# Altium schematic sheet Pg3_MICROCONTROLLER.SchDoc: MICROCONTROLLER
size 431 x 279 mm; Date: Not shown in title block; ApprovedBy: Not shown in title block; CheckedBy: Not shown in title block; Author: Not shown in title block; CompanyName: Not shown in title block; Engineer: Not shown in title block; Organization: Not shown in title block; Address1: Not shown in title block; Address2: Not shown in title block; Address3: Not shown in title block; Address4: Not shown in title block; DocumentNumber: 3; Revision: Use project parameter SCH_Rev; SheetNumber: 3; SheetTotal: 9; PageSetup: Record=PageOptions|CenterHorizontal=True|CenterVertical=True|PrintScale=1.00|XCorrection=1.00|YCorrection=1.00|PrintKind=0|BorderSize=5000000|LeftOffset=0|BottomOffset=0|Orientation=2|PaperLength=1000|PaperWidth=1000|Scale=100|PaperSource=15|PrintQuality=600|MediaType=1|DitherType=10|PaperKind=Letter|PrintScaleMode=1
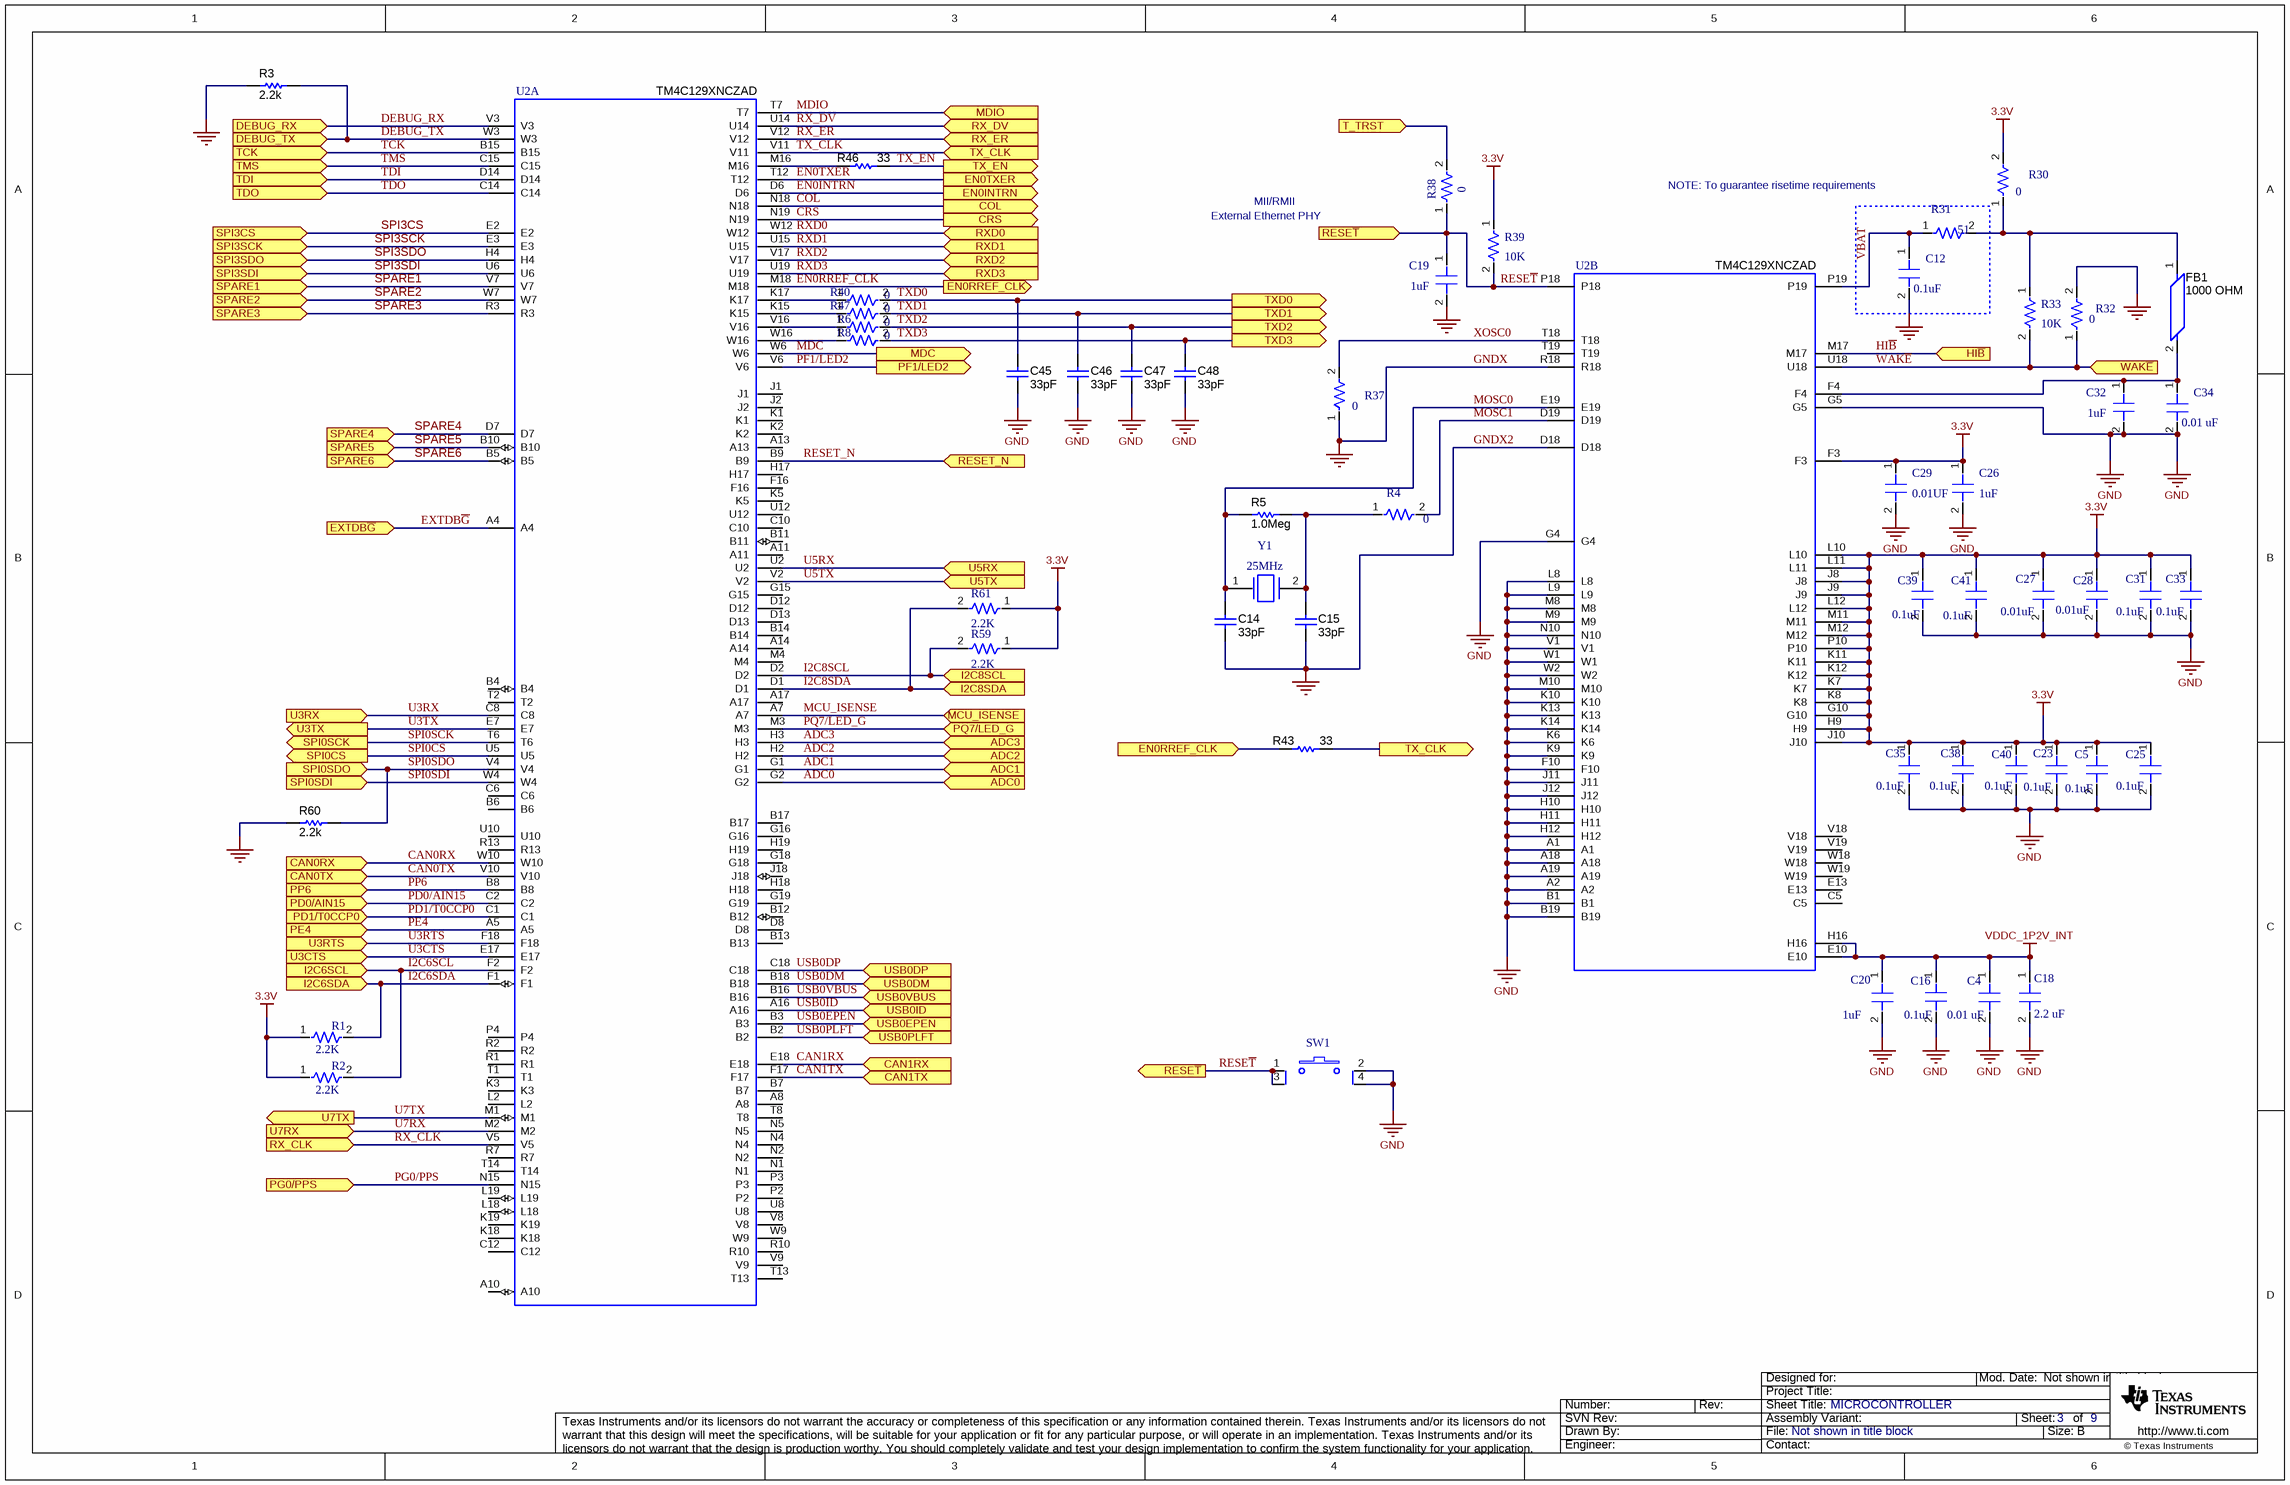
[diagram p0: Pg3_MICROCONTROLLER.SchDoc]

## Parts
C4  value 0.01 uF  [0402]  (hidden comment: CAPC0603)
C5  value 0.1uF  [0603]  (hidden comment: CAPC0603)
C12  value 0.1uF  [0603]  (hidden comment: CAPC0603)
C14  ValueDisplayed: 33pF  [0402]  (hidden comment: GRM1555C1H330JA01D)
C15  ValueDisplayed: 33pF  [0402]  (hidden comment: GRM1555C1H330JA01D)
C16  value 0.1uF  [0603]  (hidden comment: CAPC0603)
C18  value 2.2 uF  [0603]  (hidden comment: CAPC0603)
C19  value 1uF  [0402]  (hidden comment: CAPC0402)
C20  value 1uF  [0402]  (hidden comment: CAPC0402)
C23  value 0.1uF  [0603]  (hidden comment: CAPC0603)
C25  value 0.1uF  [0603]  (hidden comment: CAPC0603)
C26  value 1uF  [0402]  (hidden comment: CAPC0402)
C27  value 0.01uF  [0402]  (hidden comment: CAPC0603)
C28  value 0.01uF  [0402]  (hidden comment: CAPC0603)
C29  value 0.01UF  [0402]  (hidden comment: CAPC0402)
C31  value 0.1uF  [0402]  (hidden comment: CAPC0402)
C32  value 1uF  [0402]  (hidden comment: CAPC0402)
C33  value 0.1uF  [0402]  (hidden comment: CAPC0402)
C34  value 0.01 uF  [0402]  (hidden comment: CAPC0402)
C35  value 0.1uF  [0603]  (hidden comment: CAPC0603)
C38  value 0.1uF  [0603]  (hidden comment: CAPC0603)
C39  value 0.1uF  [0603]  (hidden comment: CAPC0603)
C40  value 0.1uF  [0603]  (hidden comment: CAPC0603)
C41  value 0.1uF  [0603]  (hidden comment: CAPC0603)
C45  ValueDisplayed: 33pF  [0402]  (hidden comment: GRM1555C1H330JA01D)
C46  ValueDisplayed: 33pF  [0402]  (hidden comment: GRM1555C1H330JA01D)
C47  ValueDisplayed: 33pF  [0402]  (hidden comment: GRM1555C1H330JA01D)
C48  ValueDisplayed: 33pF  [0402]  (hidden comment: GRM1555C1H330JA01D)
FB1  1000 OHM  [0603L]
R1  value 2.2K  [0603]  (hidden comment: RESC0603)
R2  value 2.2K  [0603]  (hidden comment: RESC0603)
R3  value 2.2k  [0402]  (hidden comment: CRCW04022K20JNED)
R4  value 0  [0402]  (hidden comment: RESC0402)
R5  value 1.0Meg  [0402]  (hidden comment: CRCW04021M00JNED)
R6  value 0  [0402]  (hidden comment: RESC0402)
R8  value 0  [0402]  (hidden comment: RESC0402)
R30  value 0  [0402]  (hidden comment: RESC0402)
R31  value 51  [0402]  (hidden comment: RESC0402)
R32  value 0  [0402]  (hidden comment: RESC0402)
R33  value 10K  [0402]  (hidden comment: RESC0402)
R37  value 0  [0402]  (hidden comment: RESC0402)
R38  value 0  [0402]  (hidden comment: RESC0402)
R39  value 10K  [0402]  (hidden comment: RESC0402)
R40  value 0  [0402]  (hidden comment: RESC0402)
R43  value 33  [0402]  (hidden comment: CRCW040233R0JNED)
R46  value 33  [0402]  (hidden comment: CRCW040233R0JNED)
R47  value 0  [0402]  (hidden comment: RESC0402)
R59  value 2.2K  [0603]  (hidden comment: RESC0603)
R60  value 2.2k  [0402]  (hidden comment: CRCW04022K20JNED)
R61  value 2.2K  [0603]  (hidden comment: RESC0603)
SW1  SW-EVQQ2  [SW-EVQQ2]  (value not drawn)
U2  Part Number: TM4C129XNCZAD  [BGA212C50P19X19_1000X1000X100]  (hidden comment: TM4C129X)  (parts A,B of 3)
Y1  value 25MHz  [XTAL-NX5032GA]  (hidden comment: XTAL-NX5032GA)

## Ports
ADC0, ADC1, ADC2, ADC3, CAN0RX, CAN0TX, CAN1RX, CAN1TX, COL, CRS, DEBUG_RX, DEBUG_TX, EN0INTRN, EN0RREF_CLK, EN0TXER, EXTDB~{G}, HI~{B}, I2C6SCL, I2C6SDA, I2C8SCL, I2C8SDA, MCU_ISENSE, MDC, MDIO, PD0/AIN15, PD1/T0CCP0, PE4, PF1/LED2, PG0/PPS, PP6, PQ7/LED_G, RESET_N, RESE~{T}, RX_CLK, RX_DV, RX_ER, RXD0, RXD1, RXD2, RXD3, SPARE1, SPARE2, SPARE3, SPARE4, SPARE5, SPARE6 (in), SPI0CS, SPI0SCK (out), SPI0SDI, SPI0SDO, SPI3CS, SPI3SCK, SPI3SDI, SPI3SDO, T_TRST, TCK, TDI, TDO, TMS, TX_CLK, TX_EN, TXD0, TXD1, TXD2, TXD3, U3CTS, U3RTS, U3RX, U3TX (out), U5RX, U5TX, U7RX, U7TX, USB0DM, USB0DP, USB0EPEN, USB0ID, USB0PLFT, USB0VBUS, WAK~{E}

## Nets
3.3V: C5.1 C23.1 C25.1 C26.1 C27.1 C28.1 C29.1 C31.1 C33.1 C35.1 C38.1 C39.1 C40.1 C41.1 R1.1 R2.1 R30.2 R39.1 R59.1 R61.1 U2.F3 U2.G10 U2.H9 U2.J8 U2.J9 U2.J10 U2.K7 U2.K8 U2.K11 U2.K12 U2.L10 U2.L11 U2.L12 U2.M11 U2.M12 U2.P10
GNDX: C4.2 C5.2 C12.2 C14.1 C15.2 C16.2 C18.2 C19.2 C20.2 C23.2 C25.2 C26.2 C27.2 C28.2 C29.2 C31.2 C32.2 C33.2 C34.2 C35.2 C38.2 C39.2 C40.2 C41.2 C45.1 C46.1 C47.1 C48.1 R3.1 R32.2 R37.1 R60.1 SW1.2 SW1.4 U2.A1 U2.A2 U2.A18 U2.A19 U2.B1 U2.B19 U2.D18 U2.F10 U2.G4 U2.G5 U2.H10 U2.H11 U2.H12 U2.J11 U2.J12 U2.K6 U2.K9 U2.K10 U2.K13 U2.K14 U2.L8 U2.L9 U2.M8 U2.M9 U2.M10 U2.N10 U2.R18 U2.V1 U2.W1 U2.W2  [also labelled GND, GNDX2]
VDDC_1P2V_INT: C4.1 C16.1 C18.1 C20.1 U2.E10 U2.H16
EXTDB~{G}: U2.A4 ; port EXTDB~{G}
HI~{B}: U2.M17 ; port HI~{B}
RESE~{T}: C19.1 R38.1 R39.2 SW1.1 SW1.3 U2.P18 ; port RESE~{T}
WAK~{E}: R32.1 R33.2 U2.U18 ; port WAK~{E}
ADC0: U2.G2 ; port ADC0
ADC1: U2.G1 ; port ADC1
ADC2: U2.H2 ; port ADC2
ADC3: U2.H3 ; port ADC3
CAN0RX: U2.W10 ; port CAN0RX
CAN0TX: U2.V10 ; port CAN0TX
CAN1RX: U2.E18 ; port CAN1RX
CAN1TX: U2.F17 ; port CAN1TX
COL: U2.N18 ; port COL
CRS: U2.N19 ; port CRS
DEBUG_RX: U2.V3 ; port DEBUG_RX
DEBUG_TX: R3.2 U2.W3 ; port DEBUG_TX
EN0INTRN: U2.D6 ; port EN0INTRN
EN0RREF_CLK: R43.1 U2.M18 ; port EN0RREF_CLK
EN0TXER: U2.T12 ; port EN0TXER
I2C6SCL: R2.2 U2.F2 ; port I2C6SCL
I2C6SDA: R1.2 U2.F1 ; port I2C6SDA
I2C8SCL: R59.2 U2.D2 ; port I2C8SCL
I2C8SDA: R61.2 U2.D1 ; port I2C8SDA
MCU_ISENSE: U2.A7 ; port MCU_ISENSE
MDC: U2.W6 ; port MDC
MDIO: U2.T7 ; port MDIO
MOSC0: C14.2 R5.1 U2.E19 Y1.1
MOSC1: R4.2 U2.D19
PD0/AIN15: U2.C2 ; port PD0/AIN15
PD1/T0CCP0: U2.C1 ; port PD1/T0CCP0
PE4: U2.A5 ; port PE4
PF1/LED2: U2.V6 ; port PF1/LED2
PG0/PPS: U2.N15 ; port PG0/PPS
PP6: U2.B8 ; port PP6
PQ7/LED_G: U2.M3 ; port PQ7/LED_G
RESET_N: U2.B9 ; port RESET_N
RX_CLK: U2.V5 ; port RX_CLK
RX_DV: U2.U14 ; port RX_DV
RX_ER: U2.V12 ; port RX_ER
RXD0: U2.W12 ; port RXD0
RXD1: U2.U15 ; port RXD1
RXD2: U2.V17 ; port RXD2
RXD3: U2.U19 ; port RXD3
SPARE1: U2.V7 ; port SPARE1
SPARE2: U2.W7 ; port SPARE2
SPARE3: U2.R3 ; port SPARE3
SPARE4: U2.D7 ; port SPARE4
SPARE5: U2.B10 ; port SPARE5
SPARE6: U2.B5 ; port SPARE6
SPI0CS: U2.U5 ; port SPI0CS
SPI0SCK: U2.T6 ; port SPI0SCK
SPI0SDI: U2.W4 ; port SPI0SDI
SPI0SDO: R60.2 U2.V4 ; port SPI0SDO
SPI3CS: U2.E2 ; port SPI3CS
SPI3SCK: U2.E3 ; port SPI3SCK
SPI3SDI: U2.U6 ; port SPI3SDI
SPI3SDO: U2.H4 ; port SPI3SDO
T_TRST: R38.2 ; port T_TRST
TCK: U2.B15 ; port TCK
TDI: U2.D14 ; port TDI
TDO: U2.C14 ; port TDO
TMS: U2.C15 ; port TMS
TX_CLK: R43.2 U2.V11 ; port TX_CLK
TX_EN: R46.2 ; port TX_EN
TXD0: C45.2 R40.2 ; port TXD0
TXD1: C46.2 R47.2 ; port TXD1
TXD2: C47.2 R6.2 ; port TXD2
TXD3: C48.2 R8.2 ; port TXD3
U3CTS: U2.E17 ; port U3CTS
U3RTS: U2.F18 ; port U3RTS
U3RX: U2.C8 ; port U3RX
U3TX: U2.E7 ; port U3TX
U5RX: U2.U2 ; port U5RX
U5TX: U2.V2 ; port U5TX
U7RX: U2.M2 ; port U7RX
U7TX: U2.M1 ; port U7TX
USB0DM: U2.B18 ; port USB0DM
USB0DP: U2.C18 ; port USB0DP
USB0EPEN: U2.B3 ; port USB0EPEN
USB0ID: U2.A16 ; port USB0ID
USB0PLFT: U2.B2 ; port USB0PLFT
USB0VBUS: U2.B16 ; port USB0VBUS
VBAT: C12.1 R31.1 U2.P19
XOSC0: R37.2 U2.T18
NetC15_1: C15.1 R4.1 R5.2 Y1.2
NetC32_1: C32.1 C34.1 FB1.2 U2.F4
NetFB1_1: FB1.1 R30.1 R31.2 R33.1
NetR6_1: R6.1 U2.V16
NetR8_1: R8.1 U2.W16
NetR40_1: R40.1 U2.K17
NetR46_1: R46.1 U2.M16
NetR47_1: R47.1 U2.K15

Not connected (* = marked no-connect by the designer): U2 A8 A10 A11 A13 A14 A17 B4 B6 B7 B11 B12 B13 B14 B17 C5 C6 C10 C12 D8 D12 D13 E13 F16 G15 G16 G18 G19 H17 H18 H19 J1 J2 J18 K1 K2 K3 K5 K18 K19 L2 L18 L19 M4 N1 N2 N4 N5 P2 P3 P4 R1 R2 R7 R10 R13 T1 T2 T8 T13 T14 T19 U8 U10 U12 V8 V9 V18 V19 W9 W18 W19

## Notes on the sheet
- External Ethernet PHY
- MII/RMII
- NOTE: To guarantee risetime requirements

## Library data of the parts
C4 = CAPC0603: Capacitor, 0.01uF 25V, 10% 0402 X7R; Part Number: TMK105B7103KV-F; PCB DECAL: CAPC0402N; GNUM: G10-C0402-C103-BBA
C5 C12 C23 C25 C35 C38-C41 = CAPC0603: Capacitor, 0.1uF 50V, 20% 0603 X7R; Part Number: C1608X7R1H104M; GNUM: G10-C0603-C104-ACA; PCB DECAL: CAPC0603L
C14 C15 C45-C48 = GRM1555C1H330JA01D: CAP, CERM, 33pF, 50V, +/-5%, C0G/NP0, 0402; Manufacturer: MuRata; Polarized: N; CompType: Capacitor; U/M: EA; Cap_F: 0.000000000033; Tolerance_%: 5; Value1: Unknown; VDC_V: 50; TaMin_C: -55; TaMax_C: 125
C16 = CAPC0603: Capacitor, 0.1uF 50V, 20% 0603 X7R; Part Number: C1608X7R1H104M; PCB DECAL: CAPC0603L; GNUM: G10-C0603-C104-ACA
C18 = CAPC0603: Capacitor, 2.2uF, 16V, 10%, 0603, X5R; Part Number: GRM188R61C225KE15D; PCB DECAL: CAPC0603L; GNUM: G10-C0603-C225-HBB
C19 C20 C26 C32 = CAPC0402: Capacitor, 1uF , X5R, 10V, 0402; Part Number: C1005X5R1A105M050BB; PCB DECAL: CAPC0402N; GNUM: G10-C0402-C105-GCB
C27 C28 = CAPC0603: Capacitor, 0.01uF 25V, 10% 0402 X7R; Part Number: TMK105B7103KV-F; PCB DECAL: CAPC0402L; GNUM: G10-C0402-C103-BBA
C29 C31 C33 = CAPC0402: Capacitor, 0.1uF 16V, 10% 0402 X7R; Part Number: EMK105B7104KV-F; PCB DECAL: CAPC0402N; GNUM: G10-C0402-C104-HBA
C34 = CAPC0402: Capacitor, 0.01uF 25V, 10% 0402 X7R; Part Number: TMK105B7103KV-F; PCB DECAL: CAPC0402N; GNUM: G10-C0402-C103-BBA
FB1 = MMZ1608B102C: FERRITE CHIP 1000 OHM 300MA 0603; Manufacturer: TDK Corporation; CompType: Ferrite Bead
R1 R2 R59 R61 = RESC0603: Resistor, 2.2K OHM 1/10W 5% 0603 SMD; Manufacturer #1: Generic; Part Number: CRCW06032K20JNEA; PCB DECAL: RESC0603N; GNUM: G11-R0603-R222-AAA; Description: Resistor,Chip;1.60mm L X 0.83mm W X 0.60mm H; Geometry.Height: 0.6mm; PCBL.Component: CHP;RESC;1500;1700;150;400;700;950;600; PCBL.Process: F;N;50;50;200;100;200;250;350;-50;0
R3 R60 = CRCW04022K20JNED: RES, 2.2k ohm, 5%, 0.063W, 0402; Manufacturer: Vishay-Dale; CompType: Resistor; Res_ohm: 2200; Value_Code: 2k20; Tolerance_%: 5; Power_W: 0.063; VDC_V: 50; TempCo: 200 ppm/C; EIA_Code: E24; U/M: EA
R4 R6 R8 R30 R32 R37 R38 R40 R47 = RESC0402: Resistor, 0 ohm, 1/10W, 5%, 0402; Manufacturer #1: Generic; Part Number: ERJ-2GE0R00X; Description: Resistor,Chip;1.00mm L X 0.5mm W X 0.35mm H; Geometry.Height: 0.35mm; PCBL.Component: CHP;RESC;1500;1700;150;400;700;950;600; PCBL.Process: F;N;50;50;200;100;200;250;350;-50;0; PCB DECAL: RESC0402N; GNUM: G11-R0402-0000-AAA
R5 = CRCW04021M00JNED: RES, 1.0Meg ohm, 5%, 0.063W, 0402; Manufacturer: Vishay-Dale; CompType: Resistor; Res_ohm: 1000000; Value_Code: 1M00; Tolerance_%: 5; Power_W: 0.063; VDC_V: 50; TempCo: 200 ppm/C; EIA_Code: E24; U/M: EA
R31 = RESC0402: Resistor, 51 ohm, 1/10W, 5%, 0402; Manufacturer #1: Generic; Part Number: ERJ-2GEJ510X; Description: Resistor,Chip;1.00mm L X 0.5mm W X 0.35mm H; Geometry.Height: 0.35mm; PCBL.Component: CHP;RESC;1500;1700;150;400;700;950;600; PCBL.Process: F;N;50;50;200;100;200;250;350;-50;0; PCB DECAL: RESC0402N; GNUM: G11-R0402-51R0-AAA
R33 R39 = RESC0402: Resistor, 10k ohm, 1/10W, 5%, 0402 Thick Film; Manufacturer #1: Generic; Part Number: RC0402FR-0710KL; Description: Resistor,Chip;1.00mm L X 0.5mm W X 0.35mm H; Geometry.Height: 0.35mm; PCBL.Component: CHP;RESC;1500;1700;150;400;700;950;600; PCBL.Process: F;N;50;50;200;100;200;250;350;-50;0; PCB DECAL: RESC0402N; GNUM: G11-R0402-1002-AAA
R43 R46 = CRCW040233R0JNED: RES, 33 ohm, 5%, 0.063W, 0402; Manufacturer: Vishay-Dale; CompType: Resistor; Value_Code: 33R0; Tolerance_%: 5; Power_W: 0.063; VDC_V: 50; TempCo: 200 ppm/C; EIA_Code: E24; U/M: EA
SW1 = SW-EVQQ2: Switch, Tact 6mm SMT, 160gf; Manufacturer #1: Panasonic; Part Number: B3S-1000; Description: Switch, Tact 6mm SMT, 50gf; GNUM: G21-4P6MM-B3S1-AAA
U2 = TM4C129X: Stellaris MCU TM4C129XNCZAD 212 BGA, super; GNUM: G50-BG212-C129-ALI; PCB DECAL: BGA19X19-05MM-T1; Geometry.Height: 50.00mil
Y1 = XTAL-NX5032GA: Crystal, 25.00MHz 5.0x3.2mm SMT; Part Number: 445I23D25M00000; Description: Crystal, 16.00MHz 5.0x3.2mm SMT; GNUM: G15-5X3P2-2506-AAA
